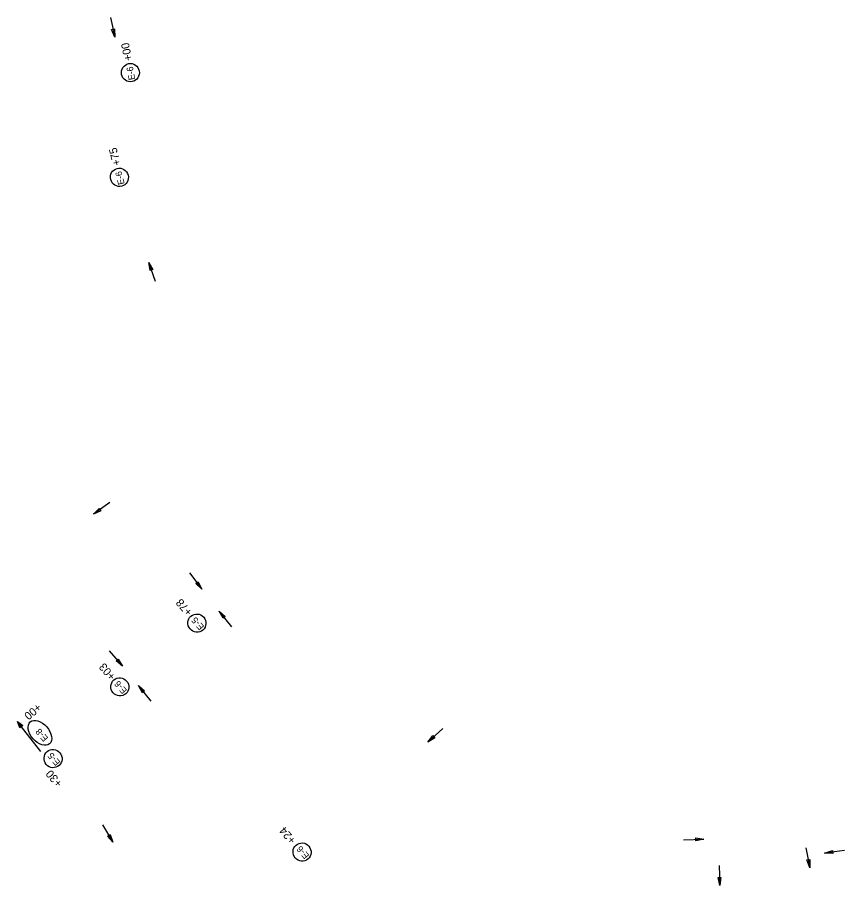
# Model space of a CAD drawing. Extents: x 918344 to 920005, y 1764082 to 1766125.
# Drawn here: x 918993 to 919613, y 1765101 to 1765752 of the extents above; entities that cross this region are included whole.
import ezdxf

# ---------------------------------------------------------------- set-up
doc = ezdxf.new("R2010")
doc.units = 0
for name, color, linetype in [('1', 7, 'Continuous'), ('43', 7, 'Continuous'), ('44', 7, 'Continuous'), ('EC_CG', 7, 'Continuous'), ('Level 1', 7, 'Continuous'), ('Level 8', 7, 'Continuous')]:
    doc.layers.add(name, color=color, linetype=linetype)

msp = doc.modelspace()

# ---------------------------------------------------------------- linework, layer by layer
at = {"layer": '1'}
msp.add_ellipse((919009.74, 1765215.41), major_axis=(-7.2, 8.26), ratio=0.622952, dxfattribs=at)
at = {"layer": '43'}
for p, q in [((919063.57, 1765742.59), (919065.66, 1765743.04)), ((919065.89, 1765736.88), (919063.57, 1765742.59)), ((919065.66, 1765743.04), (919065.89, 1765736.88)), ((919091.56, 1765568.09), (919094.54, 1765562.69)), ((919092.51, 1765562), (919091.56, 1765568.09)), ((919094.54, 1765562.69), (919092.51, 1765562)), ((919049.83, 1765379.24), (919054.19, 1765383.6)), ((919055.42, 1765381.85), (919049.83, 1765379.24)), ((919054.19, 1765383.6), (919055.42, 1765381.85)), ((919126.61, 1765327.35), (919128.32, 1765328.64)), ((919128.32, 1765328.64), (919131.12, 1765323.14)), ((919131.12, 1765323.14), (919126.61, 1765327.35)), ((919144.09, 1765306.67), (919148.79, 1765302.68)), ((919147.14, 1765301.31), (919144.09, 1765306.67)), ((919148.79, 1765302.68), (919147.14, 1765301.31)), ((919066.89, 1765269.33), (919068.51, 1765270.73)), ((919071.67, 1765265.44), (919066.89, 1765269.33)), ((919068.51, 1765270.73), (919071.67, 1765265.44)), ((919083.57, 1765250.81), (919088.28, 1765246.82)), ((919086.63, 1765245.45), (919083.57, 1765250.81)), ((919088.28, 1765246.82), (919086.63, 1765245.45)), ((919300.72, 1765208.4), (919304.49, 1765213.29)), ((919305.93, 1765211.7), (919300.72, 1765208.4)), ((919304.49, 1765213.29), (919305.93, 1765211.7)), ((919060.48, 1765138.06), (919062.33, 1765139.15)), ((919062.33, 1765139.15), (919064.49, 1765133.37)), ((919064.49, 1765133.37), (919060.48, 1765138.06)), ((919501.63, 1765134.49), (919501.56, 1765136.64)), ((919501.56, 1765136.64), (919507.67, 1765135.77)), ((919507.67, 1765135.77), (919501.63, 1765134.49)), ((919598.15, 1765125.26), (919604.04, 1765127.1)), ((919604.04, 1765127.1), (919604.32, 1765124.97)), ((919584.89, 1765120.11), (919587, 1765120.51)), ((919587.08, 1765114.34), (919584.89, 1765120.11)), ((919587, 1765120.51), (919587.08, 1765114.34)), ((919604.32, 1765124.97), (919598.15, 1765125.26)), ((919518.29, 1765106.91), (919520.44, 1765106.98)), ((919519.57, 1765100.87), (919518.29, 1765106.91)), ((919520.44, 1765106.98), (919519.57, 1765100.87))]:
    msp.add_line(p, q, dxfattribs=at)
for points in [[(919062.7, 1765751.73), (919065.89, 1765736.88)], [(919096.47, 1765553.72), (919091.56, 1765568.09)], [(919062.27, 1765387.96), (919049.83, 1765379.24)], [(919121.98, 1765335.27), (919131.12, 1765323.14)], [(919153.79, 1765294.98), (919144.09, 1765306.67)], [(919061.74, 1765276.93), (919071.67, 1765265.44)], [(919093.27, 1765239.12), (919083.57, 1765250.81)], [(919311.95, 1765218.63), (919300.72, 1765208.4)], [(919056.79, 1765146.46), (919064.49, 1765133.37)], [(919492.49, 1765135.25), (919507.67, 1765135.77)], [(919584.23, 1765129.26), (919587.08, 1765114.34)], [(919613.22, 1765127.2), (919598.15, 1765125.26)], [(919519.05, 1765116.05), (919519.57, 1765100.87)]]:
    msp.add_lwpolyline(points, dxfattribs=at)
at = {"layer": 'EC_CG'}
msp.add_ellipse((919206.35, 1765126.06), major_axis=(4.48, -5.22), ratio=0.97521, dxfattribs=at)
at = {"layer": 'Level 1'}
for centre, major_axis in [((919077.61, 1765710.3), (1.33, -6.75)), ((919069.37, 1765631.8), (1.71, -6.67)), ((919127.47, 1765297.7), (4.48, -5.22)), ((919069.7, 1765249.85), (4.48, -5.22)), ((919019.64, 1765196.08), (4.48, -5.22))]:
    msp.add_ellipse(centre, major_axis=major_axis, ratio=0.97521, dxfattribs=at)
at = {"layer": 'Level 8'}
for p, q in [((918994.93, 1765219.39), (918993.39, 1765222.69)), ((918995.23, 1765219.62), (918993.47, 1765222.73)), ((918995.51, 1765219.84), (918993.56, 1765222.79)), ((918996.1, 1765220.3), (918993.71, 1765222.91)), ((918996.38, 1765220.52), (918993.78, 1765222.97)), ((918996.68, 1765220.75), (918993.85, 1765223.05))]:
    msp.add_line(p, q, dxfattribs=at)
msp.add_lwpolyline([(918992.85, 1765223.85), (918996.97, 1765220.98), (918994.64, 1765219.16)], close=True, dxfattribs=at)
msp.add_lwpolyline([(919010.46, 1765201.51), (918997.64, 1765217.77), (918992.87, 1765223.83)], dxfattribs=at)

# ---------------------------------------------------------------- texts
at = {"layer": '1'}
msp.add_text('E-8 ', height=4.876, rotation=131.04792, dxfattribs=at).set_placement((919016.31, 1765211.52))
at = {"layer": '44'}
for s, rotation, p in [('+00', 101.09655, (919079, 1765719.79)), ('+75', 104.31387, (919070.51, 1765641.41)), ('+78', 130.58924, (919124.59, 1765306.18)), ('+03', 130.58924, (919066.93, 1765257.96)), ('+00', 219.72636, (919007.87, 1765237.89)), ('+30', 130.58924, (919027, 1765177.82))]:
    msp.add_text(s, height=6, rotation=rotation, dxfattribs=at).set_placement(p)
at = {"layer": 'EC_CG'}
for s, height, rotation, p in [('+24', 6, 130.55409, (919202.13, 1765135.21)), ('E-6', 4.876, 130.61211, (919212.05, 1765123.48))]:
    msp.add_text(s, height=height, rotation=rotation, dxfattribs=at).set_placement(p)
at = {"layer": 'Level 1'}
for s, rotation, p in [('E-6', 101.15458, (919081.31, 1765705.25)), ('E-6', 104.37189, (919073.34, 1765626.97)), ('E-5', 130.64727, (919133.26, 1765295.02)), ('E-6', 130.64727, (919075.4, 1765247.28)), ('E-5', 130.64727, (919025.43, 1765193.4))]:
    msp.add_text(s, height=4.876, rotation=rotation, dxfattribs=at).set_placement(p)

doc.saveas('drawing.dxf')
